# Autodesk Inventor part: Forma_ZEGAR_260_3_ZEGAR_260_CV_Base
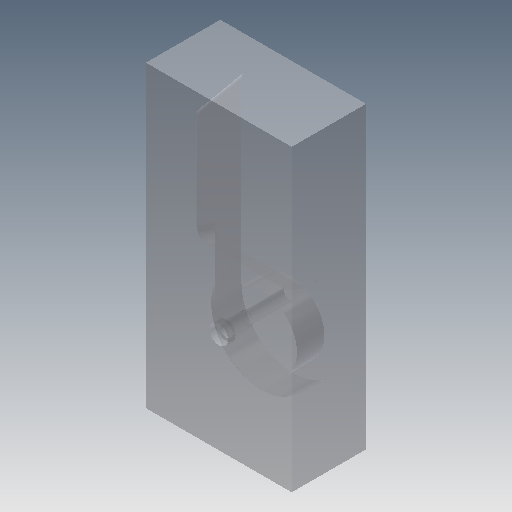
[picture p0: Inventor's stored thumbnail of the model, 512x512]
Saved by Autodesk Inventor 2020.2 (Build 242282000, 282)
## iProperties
Created: 2015-01
Part Number: Forma_ZEGAR_260_3_ZEGAR_260_CV_Base
Material: Ogólny
Document SubType Name: Modeling
Designer: F.Stasiak
Density: 1 g/cm^3
Appearance: Domyślna
Catalog Web Link: www.expertbooks.pl
Manager: www.cadconsulting.pl
Company: Fabian Stasiak CAD Consulting
Author: F.Stasiak
Subject: Zbiór ćwiczeń. Autodesk Inventor 2020. Kurs Professional
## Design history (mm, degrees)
node "Forma_ZEGAR_260_3_ZEGAR_260_MP"
sketch "Szkic2"
  geometry: 1 further point
hole "Otwór2" sketch "Szkic2" at (39, -106.407) diameter "d7" = 7; stored, may be unused: countersink angle "d11" = 90 deg, drill point angle "d13" = 118 deg; dims "d8" = 6, "d9" = 10, "d10" = 4, "d12" = 15
feature "Rzeźbienie3"
feature "Bryła4::Forma_ZEGAR_260_3_ZEGAR_260_MP"
tag "Bryła wyprowadzona1"
node "Bryła1"
feature "Forma_ZEGAR_260_3_ZEGAR_260_MP_Bodies"
feature "Powierzchnia3"
body "Srf3"
